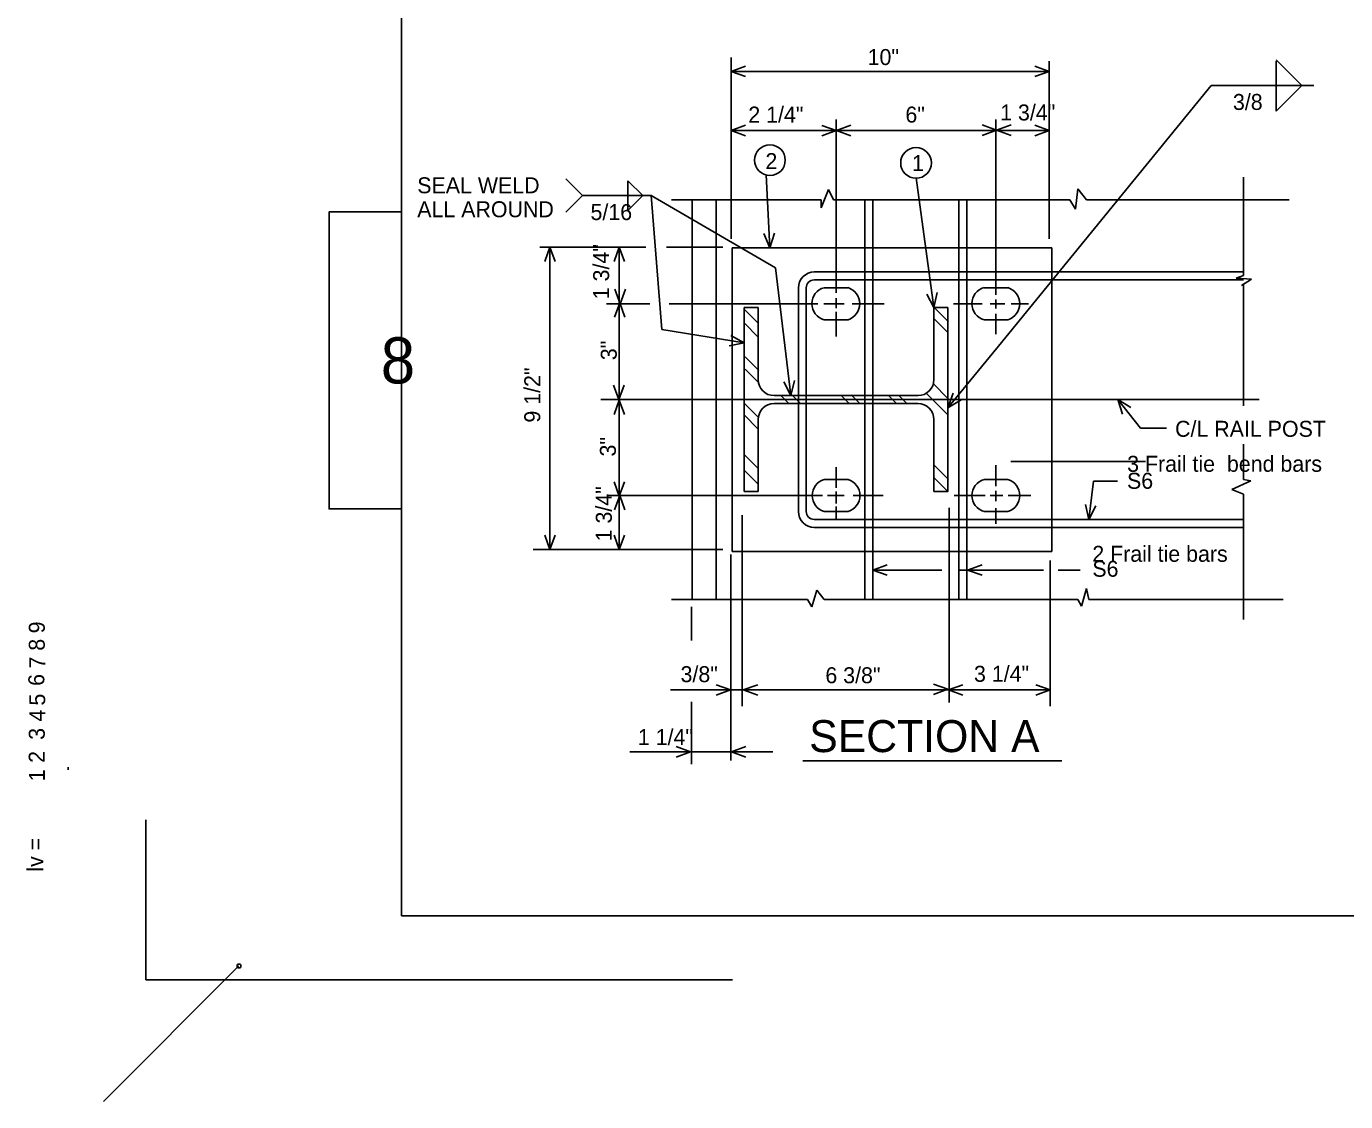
# Model space of a CAD drawing. Extents: x 1509.2 to 1521.3, y 1506 to 1514.6.
# Drawn here: x 1509.276 to 1512.715, y 1506.447 to 1509.25 of the extents above; entities that cross this region are included whole.
import ezdxf

# ---------------------------------------------------------------- set-up
doc = ezdxf.new("R2010")
doc.units = 0
for name, color, linetype in [('Level 1', 7, 'Continuous'), ('Level 2', 7, 'Continuous'), ('Level 3', 7, 'Continuous'), ('Level 4', 7, 'Continuous'), ('Level 49', 7, 'Continuous'), ('Level 5', 7, 'Continuous'), ('Level 50', 7, 'Continuous'), ('Level 6', 7, 'Continuous'), ('Level 7', 7, 'Continuous'), ('Level 8', 7, 'Continuous'), ('Level 9', 7, 'Continuous')]:
    doc.layers.add(name, color=color, linetype=linetype)

msp = doc.modelspace()

# ---------------------------------------------------------------- linework, layer by layer
at = {"layer": 'Level 1'}
for p, q in [((1510.2539, 1506.9309), (1510.2539, 1513.9308)), ((1509.3847, 1507.3188), (1509.3847, 1507.3116)), ((1509.5873, 1507.1817), (1509.5873, 1506.7643)), ((1510.2539, 1506.9309), (1520.7124, 1506.9309)), ((1509.5873, 1506.7643), (1511.1166, 1506.7643))]:
    msp.add_line(p, q, dxfattribs=at)
msp.add_lwpolyline([(1510.2539, 1508.7659), (1510.0647, 1508.7659), (1510.0647, 1507.992), (1510.2539, 1507.992)], close=True, dxfattribs=at)
at = {"layer": 'Level 2'}
for p, q in [((1511.113, 1508.696), (1511.113, 1509.1683)), ((1511.113, 1509.1323), (1511.1506, 1509.1459)), ((1511.113, 1509.1323), (1511.1506, 1509.1459)), ((1511.9419, 1509.1323), (1511.9043, 1509.1459)), ((1511.942, 1508.696), (1511.942, 1509.1588)), ((1512.5335, 1509.1626), (1512.5987, 1509.0973)), ((1512.5335, 1509.159), (1512.5335, 1509.0286)), ((1511.113, 1509.1323), (1511.9419, 1509.1323)), ((1511.113, 1509.1323), (1511.1506, 1509.1186)), ((1511.113, 1509.1323), (1511.1506, 1509.1186)), ((1511.9419, 1509.1323), (1511.9043, 1509.1186)), ((1511.8019, 1508.4068), (1512.3644, 1509.0956)), ((1512.3644, 1509.0956), (1512.6323, 1509.0956)), ((1512.5335, 1509.0286), (1512.5987, 1509.0938)), ((1511.3865, 1508.5549), (1511.3865, 1509.0069)), ((1511.8033, 1508.5501), (1511.8033, 1509.0069)), ((1511.113, 1508.978), (1511.1506, 1508.9917)), ((1511.113, 1508.978), (1511.1506, 1508.9917)), ((1511.113, 1508.978), (1511.9421, 1508.978)), ((1511.113, 1508.978), (1511.1506, 1508.9643)), ((1511.113, 1508.978), (1511.1506, 1508.9643)), ((1511.3867, 1508.9779), (1511.3491, 1508.9916)), ((1511.3867, 1508.9779), (1511.3491, 1508.9643)), ((1511.3873, 1508.978), (1511.4248, 1508.9917)), ((1511.3873, 1508.978), (1511.4248, 1508.9643)), ((1511.8046, 1508.979), (1511.767, 1508.9927)), ((1511.8046, 1508.979), (1511.767, 1508.9653)), ((1511.8052, 1508.979), (1511.8428, 1508.9927)), ((1511.8052, 1508.979), (1511.8428, 1508.9653)), ((1511.9421, 1508.978), (1511.9045, 1508.9917)), ((1511.9421, 1508.978), (1511.9045, 1508.9643)), ((1510.6818, 1508.8523), (1510.7255, 1508.8086)), ((1510.8824, 1508.8086), (1510.8437, 1508.8473)), ((1510.8437, 1508.7699), (1510.8437, 1508.8473)), ((1511.2142, 1508.6725), (1511.2046, 1508.8623)), ((1511.6418, 1508.5164), (1511.595, 1508.8551)), ((1512.449, 1508.5999), (1512.449, 1508.8569)), ((1510.6818, 1508.7649), (1510.7255, 1508.8086)), ((1510.9044, 1508.8086), (1510.7255, 1508.8086)), ((1510.8824, 1508.8086), (1510.8437, 1508.7699)), ((1511.2284, 1508.6201), (1510.9044, 1508.8086)), ((1510.9326, 1508.4598), (1510.9044, 1508.8086)), ((1510.9578, 1508.7975), (1511.3473, 1508.7975)), ((1511.0115, 1507.7559), (1511.0115, 1508.7975)), ((1511.074, 1507.7559), (1511.074, 1508.7975)), ((1511.3473, 1508.7764), (1511.3667, 1508.8246)), ((1511.3473, 1508.7975), (1511.3473, 1508.7764)), ((1511.3667, 1508.8246), (1511.3795, 1508.7975)), ((1511.3795, 1508.7975), (1511.9958, 1508.7975)), ((1511.4613, 1507.7559), (1511.4613, 1508.7974)), ((1511.4822, 1507.7559), (1511.4822, 1508.7974)), ((1511.707, 1507.7559), (1511.707, 1508.7974)), ((1511.7278, 1507.7559), (1511.7278, 1508.7974)), ((1511.9958, 1508.7975), (1512.0103, 1508.7733)), ((1512.0103, 1508.7733), (1512.0167, 1508.8262)), ((1512.0167, 1508.8262), (1512.0392, 1508.7975)), ((1512.0392, 1508.7975), (1512.5674, 1508.7975)), ((1511.2142, 1508.6725), (1511.1986, 1508.7093)), ((1511.2142, 1508.6725), (1511.2259, 1508.7108)), ((1510.8905, 1508.6743), (1510.6141, 1508.6743)), ((1510.6406, 1508.6743), (1510.6269, 1508.6367)), ((1510.6406, 1507.8863), (1510.6406, 1508.6743)), ((1510.6406, 1508.6743), (1510.6543, 1508.6367)), ((1510.8213, 1508.6743), (1510.8077, 1508.6367)), ((1510.8213, 1507.8863), (1510.8213, 1508.6743)), ((1510.8213, 1508.6743), (1510.835, 1508.6367)), ((1511.0913, 1508.6743), (1510.9442, 1508.6743)), ((1511.1157, 1508.6725), (1511.949, 1508.6725)), ((1511.1157, 1507.8808), (1511.1157, 1508.6725)), ((1511.949, 1507.8808), (1511.949, 1508.6725)), ((1511.269, 1508.2872), (1511.2284, 1508.6201)), ((1511.2284, 1508.6201), (1511.2284, 1508.6201)), ((1511.3298, 1508.6095), (1512.449, 1508.6095)), ((1512.449, 1508.5999), (1512.4292, 1508.5935)), ((1512.4292, 1508.5935), (1512.4693, 1508.5903)), ((1510.8238, 1508.5268), (1510.8101, 1508.5643)), ((1510.8238, 1508.5268), (1510.8374, 1508.5643)), ((1511.2882, 1507.9853), (1511.2882, 1508.5678)), ((1511.3089, 1507.9852), (1511.3089, 1508.5678)), ((1511.3298, 1508.5887), (1512.449, 1508.5887)), ((1511.3554, 1508.5685), (1511.4178, 1508.5685)), ((1511.7722, 1508.5685), (1511.8345, 1508.5685)), ((1512.4693, 1508.5903), (1512.4436, 1508.5743)), ((1512.449, 1508.2602), (1512.449, 1508.579)), ((1510.7882, 1508.5268), (1510.9013, 1508.5268)), ((1510.8225, 1508.5288), (1510.8088, 1508.4913)), ((1510.8225, 1508.5288), (1510.8362, 1508.4913)), ((1510.9513, 1508.5268), (1511.3394, 1508.5268)), ((1511.3547, 1508.5268), (1511.4075, 1508.5268)), ((1511.3865, 1508.515), (1511.3865, 1508.5408)), ((1511.4286, 1508.5268), (1511.5118, 1508.5268)), ((1511.6418, 1508.5164), (1511.6232, 1508.5518)), ((1511.6418, 1508.5164), (1511.6503, 1508.5555)), ((1511.6931, 1508.5268), (1511.7672, 1508.5268)), ((1511.7883, 1508.5268), (1511.8262, 1508.5268)), ((1511.8033, 1508.5138), (1511.8033, 1508.5379)), ((1511.8428, 1508.5268), (1511.8881, 1508.5268)), ((1511.147, 1508.0372), (1511.147, 1508.5164)), ((1511.147, 1508.5164), (1511.1835, 1508.5164)), ((1511.1835, 1508.4758), (1511.148, 1508.5113)), ((1511.1835, 1508.3288), (1511.1835, 1508.5164)), ((1511.3865, 1508.4411), (1511.3865, 1508.5057)), ((1511.677, 1508.4525), (1511.6415, 1508.488)), ((1511.6418, 1508.5164), (1511.6783, 1508.5164)), ((1511.6418, 1508.3288), (1511.6418, 1508.5164)), ((1511.6797, 1508.4793), (1511.6442, 1508.5148)), ((1511.6783, 1508.0372), (1511.6783, 1508.5164)), ((1511.8033, 1508.4473), (1511.8033, 1508.5002)), ((1511.147, 1508.4246), (1510.9326, 1508.4598)), ((1511.1829, 1508.4406), (1511.1474, 1508.4761)), ((1511.3554, 1508.4851), (1511.4178, 1508.4851)), ((1511.7722, 1508.4851), (1511.8345, 1508.4851)), ((1511.147, 1508.4246), (1511.1077, 1508.4172)), ((1511.147, 1508.4246), (1511.1122, 1508.4442)), ((1511.1848, 1508.3524), (1511.1493, 1508.3879)), ((1511.6783, 1508.2555), (1511.8054, 1508.4111)), ((1511.1848, 1508.3203), (1511.1493, 1508.3558)), ((1511.269, 1508.2872), (1511.2508, 1508.3228)), ((1511.269, 1508.2872), (1511.278, 1508.3262)), ((1511.6783, 1508.2798), (1511.6397, 1508.3184)), ((1510.8202, 1508.2769), (1510.8065, 1508.3145)), ((1510.8202, 1508.2769), (1510.8338, 1508.3145)), ((1511.2252, 1508.2872), (1511.6002, 1508.2872)), ((1511.2638, 1508.2664), (1511.2421, 1508.2881)), ((1511.2936, 1508.2664), (1511.2719, 1508.2881)), ((1511.4204, 1508.2664), (1511.3988, 1508.2881)), ((1511.4478, 1508.2671), (1511.4262, 1508.2888)), ((1511.5443, 1508.2664), (1511.5227, 1508.2881)), ((1511.5711, 1508.2664), (1511.5494, 1508.2881)), ((1511.6783, 1508.2368), (1511.6218, 1508.2934)), ((1511.6783, 1508.2555), (1511.6915, 1508.2933)), ((1510.7732, 1508.2768), (1512.4893, 1508.2768)), ((1510.8213, 1508.2755), (1510.8077, 1508.2379)), ((1510.8213, 1508.2755), (1510.835, 1508.2379)), ((1511.1835, 1508.2309), (1511.148, 1508.2664)), ((1511.2252, 1508.2664), (1511.6002, 1508.2664)), ((1511.6783, 1508.2555), (1511.7127, 1508.2759)), ((1512.1801, 1508.2026), (1512.1207, 1508.2768)), ((1512.1207, 1508.2768), (1512.1335, 1508.2388)), ((1512.1207, 1508.2768), (1512.1548, 1508.256)), ((1511.1829, 1508.2006), (1511.1474, 1508.2361)), ((1511.1835, 1508.0372), (1511.1835, 1508.2248)), ((1511.6418, 1508.0372), (1511.6418, 1508.2248)), ((1512.1801, 1508.2026), (1512.2476, 1508.2026)), ((1512.449, 1508.0687), (1512.449, 1508.1604)), ((1511.1835, 1508.0975), (1511.148, 1508.133)), ((1511.8422, 1508.1158), (1512.193, 1508.1158)), ((1511.1835, 1508.0564), (1511.148, 1508.0919)), ((1511.3865, 1508.047), (1511.3865, 1508.101)), ((1511.6797, 1508.0689), (1511.6409, 1508.1076)), ((1511.8033, 1508.0511), (1511.8033, 1508.1061)), ((1510.8213, 1508.0247), (1510.8077, 1508.0623)), ((1510.8213, 1508.0247), (1510.835, 1508.0623)), ((1511.3554, 1508.0684), (1511.4178, 1508.0684)), ((1511.6785, 1508.0368), (1511.643, 1508.0723)), ((1511.7722, 1508.0684), (1511.8345, 1508.0684)), ((1512.0459, 1507.9643), (1512.0574, 1508.0646)), ((1512.0574, 1508.0646), (1512.1206, 1508.0646)), ((1512.4677, 1508.0654), (1512.4185, 1508.0421)), ((1512.4185, 1508.0421), (1512.449, 1508.0301)), ((1512.449, 1508.0687), (1512.4677, 1508.0654)), ((1510.7905, 1508.0267), (1511.3512, 1508.0267)), ((1510.8225, 1508.0268), (1510.8088, 1507.9893)), ((1510.8225, 1508.0268), (1510.8362, 1507.9893)), ((1511.147, 1508.0372), (1511.1835, 1508.0372)), ((1511.3641, 1508.0267), (1511.4075, 1508.0267)), ((1511.3865, 1508.0059), (1511.3865, 1508.0376)), ((1511.4309, 1508.0267), (1511.5095, 1508.0267)), ((1511.6418, 1508.0372), (1511.6783, 1508.0372)), ((1511.6948, 1508.0267), (1511.7748, 1508.0267)), ((1511.7883, 1508.0267), (1511.8216, 1508.0267)), ((1511.8033, 1508.0118), (1511.8033, 1508.039)), ((1511.8352, 1508.0267), (1511.8942, 1508.0267)), ((1512.449, 1507.7035), (1512.449, 1508.0301)), ((1511.1419, 1507.9754), (1511.1419, 1507.4778)), ((1511.3554, 1507.985), (1511.4178, 1507.985)), ((1511.3865, 1507.9661), (1511.3865, 1507.9978)), ((1511.6818, 1507.9947), (1511.6818, 1507.4874)), ((1511.7722, 1507.985), (1511.8345, 1507.985)), ((1511.8033, 1507.9528), (1511.8033, 1507.9937)), ((1512.0459, 1507.9643), (1512.0366, 1508.0033)), ((1512.0459, 1507.9643), (1512.0638, 1508.0001)), ((1511.3298, 1507.9643), (1512.449, 1507.9643)), ((1511.3298, 1507.9436), (1512.449, 1507.9436)), ((1510.6406, 1507.8863), (1510.6269, 1507.9238)), ((1510.6406, 1507.8863), (1510.6543, 1507.9238)), ((1510.8213, 1507.8863), (1510.8077, 1507.9238)), ((1510.8213, 1507.8863), (1510.835, 1507.9238)), ((1511.0913, 1507.8863), (1510.5973, 1507.8863)), ((1511.1126, 1507.8728), (1511.1126, 1507.3361)), ((1511.1157, 1507.8808), (1511.949, 1507.8808)), ((1511.4822, 1507.8326), (1511.5198, 1507.8463)), ((1511.7295, 1507.8326), (1511.7671, 1507.8463)), ((1511.9444, 1507.8573), (1511.9444, 1507.4778)), ((1511.4822, 1507.8326), (1511.6624, 1507.8326)), ((1511.4822, 1507.8326), (1511.5198, 1507.8189)), ((1511.7065, 1507.8326), (1511.927, 1507.8326)), ((1511.7295, 1507.8326), (1511.7671, 1507.8189)), ((1511.9653, 1507.8326), (1512.0228, 1507.8326)), ((1511.3233, 1507.7364), (1511.3362, 1507.7798)), ((1511.3362, 1507.7798), (1511.3554, 1507.7559)), ((1512.0263, 1507.738), (1512.0392, 1507.7846)), ((1512.0392, 1507.7846), (1512.0456, 1507.7559)), ((1510.9578, 1507.7559), (1511.3121, 1507.7559)), ((1511.0093, 1507.7367), (1511.0093, 1507.6485)), ((1511.3121, 1507.7559), (1511.3233, 1507.7364)), ((1511.3554, 1507.7559), (1512.0167, 1507.7559)), ((1512.0167, 1507.7559), (1512.0263, 1507.738)), ((1512.0456, 1507.7559), (1512.5523, 1507.7559)), ((1511.1114, 1507.5199), (1511.0738, 1507.5336)), ((1511.1447, 1507.5199), (1511.1823, 1507.5336)), ((1511.6781, 1507.5218), (1511.6405, 1507.5355)), ((1511.6797, 1507.5199), (1511.7173, 1507.5336)), ((1511.9446, 1507.5199), (1511.907, 1507.5336)), ((1510.9548, 1507.5199), (1511.9446, 1507.5199)), ((1511.1114, 1507.5199), (1511.0738, 1507.5063)), ((1511.1447, 1507.5199), (1511.1823, 1507.5063)), ((1511.6781, 1507.5218), (1511.6405, 1507.5082)), ((1511.6797, 1507.5199), (1511.7173, 1507.5063)), ((1511.9446, 1507.5199), (1511.907, 1507.5063)), ((1511.0093, 1507.4893), (1511.0093, 1507.3263)), ((1510.8493, 1507.3584), (1511.2214, 1507.3584)), ((1511.0069, 1507.3588), (1510.9693, 1507.3725)), ((1511.0069, 1507.3588), (1510.9693, 1507.3452)), ((1511.1138, 1507.3588), (1511.1514, 1507.3725)), ((1511.1138, 1507.3588), (1511.1514, 1507.3452)), ((1511.3003, 1507.3353), (1511.9748, 1507.3353)), ((1509.4764, 1506.4471), (1509.83, 1506.8006))]:
    msp.add_line(p, q, dxfattribs=at)
for centre in [(1511.2142, 1508.9008), (1511.595, 1508.8936)]:
    msp.add_circle(centre, 0.04, dxfattribs=at)
for centre, radius, start, end in [((1511.3299, 1508.5678), 0.0417, 90, 180), ((1511.3297, 1508.5679), 0.0208, 90, 180), ((1511.3667, 1508.5268), 0.0432, 105.151, 254.849), ((1511.4048, 1508.5268), 0.0437, 287.2, 72.8), ((1511.784, 1508.5268), 0.0434, 105.8765, 254.1235), ((1511.8216, 1508.5268), 0.0437, 287.2, 72.8), ((1511.2252, 1508.3289), 0.0417, 180, 270), ((1511.6001, 1508.3289), 0.0417, 270, 0), ((1511.2252, 1508.2247), 0.0417, 90, 180), ((1511.6001, 1508.2247), 0.0417, 0, 90), ((1511.3677, 1508.0267), 0.0435, 106.4619, 253.5381), ((1511.4052, 1508.0267), 0.0436, 286.7563, 73.2437), ((1511.784, 1508.0267), 0.0434, 105.8765, 254.1235), ((1511.8221, 1508.0267), 0.0435, 286.609, 73.391), ((1511.3299, 1507.9853), 0.0417, 180, 270), ((1511.3297, 1507.9851), 0.0208, 180, 270)]:
    msp.add_arc(centre, radius, start, end, dxfattribs=at)
at = {"layer": 'Level 49'}
msp.add_circle((1509.83, 1506.8006), 0.00506, dxfattribs=at)

# ---------------------------------------------------------------- texts
at = {"layer": 'Level 1'}
msp.add_text('8', height=0.1204, dxfattribs=at).set_placement((1510.1996, 1508.3187))
msp.add_text('1', height=0.0417, rotation=90, dxfattribs=at).set_placement((1509.324, 1507.282))
at = {"layer": 'Level 2'}
for s, height, rotation, p in [('10"', 0.04167, 0, (1511.4688, 1509.1488)), ('3/8', 0.04167, 0, (1512.4212, 1509.0317)), ('1 3/4"', 0.04167, 0, (1511.8143, 1509.0043)), ('2', 0.0417, 0, (1511.2023, 1508.8775)), ('1', 0.0417, 0, (1511.5845, 1508.8723)), ('SEAL WELD', 0.04167, 0, (1510.2947, 1508.8145)), ('ALL AROUND', 0.04167, 0, (1510.2947, 1508.752)), ('5/16', 0.04167, 0, (1510.7464, 1508.7447)), ('1 3/4"', 0.04167, 90, (1510.7949, 1508.5383)), ('3"', 0.04167, 90, (1510.8148, 1508.3795)), ('9 1/2"', 0.04167, 90, (1510.6154, 1508.2168)), ('C/L RAIL POST', 0.041667, 0, (1512.2703, 1508.1798)), ('3"', 0.04167, 90, (1510.8125, 1508.1285)), ('1 3/4"', 0.04167, 90, (1510.8019, 1507.9073)), ('3/8"', 0.04167, 0, (1510.9811, 1507.5403)), ('6 3/8"', 0.04167, 0, (1511.3587, 1507.5375)), ('3 1/4"', 0.04167, 0, (1511.7461, 1507.5413)), ('SECTION A', 0.08333, 0, (1511.3165, 1507.358)), ('1 1/4"', 0.04167, 0, (1510.8698, 1507.3764)), ('2', 0.0417, 90, (1509.3235, 1507.3299)), ('lv =', 0.04167, 90, (1509.3196, 1507.0464))]:
    msp.add_text(s, height=height, rotation=rotation, dxfattribs=at).set_placement(p)
for s, p in [('2 1/4"', (1511.1578, 1508.9988)), ('6"', (1511.5673, 1508.9988)), ('S6  ', (1512.145, 1508.0443)), ('S6  ', (1512.0546, 1507.8151))]:
    msp.add_text(s, height=0.04167, dxfattribs=at).set_placement(p)
at = {"layer": 'Level 3'}
msp.add_text('3', height=0.0417, rotation=90, dxfattribs=at).set_placement((1509.3237, 1507.39))
at = {"layer": 'Level 4'}
msp.add_text('4', height=0.0417, rotation=90, dxfattribs=at).set_placement((1509.3249, 1507.4377))
at = {"layer": 'Level 5'}
msp.add_text('5', height=0.0417, rotation=90, dxfattribs=at).set_placement((1509.3249, 1507.4793))
at = {"layer": 'Level 50'}
for s, p in [('3 Frail tie  bend bars', (1512.1454, 1508.0886)), ('2 Frail tie bars', (1512.0545, 1507.854))]:
    msp.add_text(s, height=0.041667, dxfattribs=at).set_placement(p)
at = {"layer": 'Level 6'}
msp.add_text('6', height=0.0417, rotation=90, dxfattribs=at).set_placement((1509.3225, 1507.5306))
at = {"layer": 'Level 7'}
msp.add_text('7', height=0.0417, rotation=90, dxfattribs=at).set_placement((1509.3249, 1507.5758))
at = {"layer": 'Level 8'}
msp.add_text('8', height=0.0417, rotation=90, dxfattribs=at).set_placement((1509.3237, 1507.6223))
at = {"layer": 'Level 9'}
msp.add_text('9', height=0.0417, rotation=90, dxfattribs=at).set_placement((1509.3237, 1507.6675))

doc.saveas('drawing.dxf')
